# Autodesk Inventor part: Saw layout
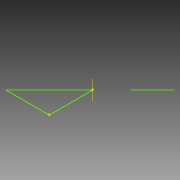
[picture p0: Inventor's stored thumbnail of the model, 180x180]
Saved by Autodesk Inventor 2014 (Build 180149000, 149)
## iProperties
Created: 2008-06
Part Number: Saw layout
Document SubType Name: Modeling
Designer: tangg
Density: 1 g/cm^3
Material: Generic
Appearance: Default
Author: tangg
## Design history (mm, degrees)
sketch "Sketch4"
  geometry: L1 (-82.286, -169.129)-(-38.592, -125.435); L2 (0, -86.843)-(86.843, 0); L3 (0, 0)-(0, -86.843); L4 (0, 0)-(86.843, 0)
  constraints: 8 end point
workpoint "Work Point4"
  workaxis "Work Axis2"
workplane "Work Plane2"
other parameters: "d1" = 45 deg
